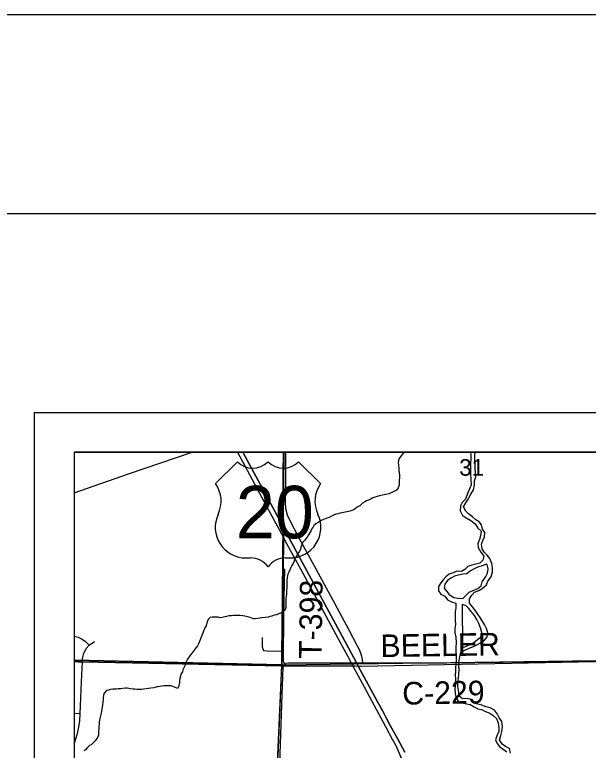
# Model space of a CAD drawing. Extents: x 0 to 34, y 0 to 22.
# Drawn here: x 1.951 to 3.392, y 20.151 to 22 of the extents above; entities that cross this region are included whole.
import ezdxf

# ---------------------------------------------------------------- set-up
doc = ezdxf.new("R2010")
doc.units = 0
for name, color, linetype in [('Default', 7, 'Continuous'), ('GM_X_County_Road', 7, 'Continuous'), ('GM_X_County_Road_Text', 7, 'Continuous'), ('GM_X_Minor_River', 7, 'Continuous'), ('GM_X_Rail_Line', 7, 'Continuous'), ('GM_X_Section', 7, 'Continuous'), ('GM_X_Section_Text', 7, 'Continuous'), ('GM_X_State_Route', 7, 'Continuous'), ('GM_X_Township', 7, 'Continuous'), ('GM_X_Township_Road', 7, 'Continuous'), ('GM_X_Township_Road_Text', 7, 'Continuous'), ('GM_X_US_Location', 7, 'Continuous'), ('GM_X_US_Route', 7, 'Continuous'), ('GM_X_US_Shield', 7, 'Continuous'), ('SH_Border', 7, 'Continuous'), ('SH_Cut_Line', 7, 'Continuous'), ('SH_Data', 7, 'Continuous')]:
    doc.layers.add(name, color=color, linetype=linetype)

msp = doc.modelspace()

# ---------------------------------------------------------------- linework, layer by layer
at = {"layer": 'Default'}
for points in [[(2.6268, 20.9), (2.1, 20.9), (2.1, 20.3771), (2.6217, 20.3656)], [(3.5755, 20.9), (2.6268, 20.9), (2.6217, 20.3656), (3.5337, 20.3786), (3.5682, 20.3787)], [(2.1, 20.3771), (2.1, 19.4698), (2.5849, 19.435), (2.5858, 19.465), (2.6217, 20.3656)]]:
    msp.add_lwpolyline(points, close=True, dxfattribs=at)
at = {"layer": 'GM_X_County_Road'}
for points in [[(2.6318, 20.8381), (2.6319, 20.845), (2.6325, 20.9)], [(2.8252, 20.371), (2.8244, 20.3793), (2.8229, 20.3867), (2.8211, 20.3926), (2.8169, 20.4035), (2.8116, 20.4141), (2.8023, 20.4319), (2.7893, 20.4563), (2.7742, 20.4842), (2.7549, 20.5196), (2.7291, 20.5675), (2.6991, 20.6232), (2.6702, 20.6767), (2.6452, 20.7228), (2.636, 20.7416), (2.6318, 20.7577), (2.6309, 20.7748), (2.6318, 20.8381)], [(2.6108, 19.9494), (2.6132, 19.9909), (2.6147, 20.0477), (2.6187, 20.1666), (2.6231, 20.2904), (2.6255, 20.36), (2.6264, 20.3623)], [(2.6264, 20.3623), (2.6267, 20.3631), (2.6272, 20.3641), (2.6302, 20.3677), (2.6333, 20.3698), (2.6391, 20.3707), (2.7004, 20.3706), (2.774, 20.3708), (2.7959, 20.3711), (2.8099, 20.3709), (2.8252, 20.371)], [(2.8252, 20.371), (3.0357, 20.3712), (3.3911, 20.375), (3.494, 20.3761), (3.5359, 20.3762)]]:
    msp.add_lwpolyline(points, dxfattribs=at)
at = {"layer": 'GM_X_Minor_River'}
msp.add_line((3.0747, 20.5174), (3.0759, 20.4092), dxfattribs=at)
for points in [[(2.9285, 20.9), (2.9251, 20.8954), (2.9209, 20.8901), (2.917, 20.8845), (2.9151, 20.8795), (2.9146, 20.8735), (2.9149, 20.8682), (2.9156, 20.8587), (2.9159, 20.8545), (2.9166, 20.8488), (2.9173, 20.8427), (2.9171, 20.823), (2.9166, 20.8173), (2.9147, 20.8108), (2.9104, 20.8048), (2.902, 20.8003), (2.8967, 20.7985), (2.8906, 20.7955), (2.8837, 20.7937), (2.875, 20.7919), (2.8678, 20.7908), (2.8617, 20.789), (2.8556, 20.7872), (2.851, 20.7853), (2.8461, 20.7831), (2.84, 20.7801), (2.8346, 20.7779), (2.8304, 20.7753), (2.8251, 20.7723), (2.8189, 20.7663), (2.8128, 20.7626), (2.8082, 20.7592), (2.8029, 20.7551), (2.7983, 20.7536), (2.7941, 20.7522), (2.7854, 20.75), (2.7812, 20.7493), (2.7732, 20.7482), (2.7679, 20.7467), (2.7633, 20.7457), (2.758, 20.7442), (2.7515, 20.7416), (2.7469, 20.7394), (2.7412, 20.7364), (2.7355, 20.7346), (2.7313, 20.7331), (2.7271, 20.7312), (2.721, 20.7286), (2.7134, 20.7238), (2.7073, 20.7201), (2.7027, 20.7163), (2.6996, 20.7114), (2.6957, 20.7061), (2.6945, 20.7016), (2.6918, 20.6971), (2.6887, 20.6922), (2.686, 20.6869), (2.6822, 20.6824), (2.6787, 20.6782), (2.6749, 20.6741), (2.6725, 20.6684), (2.6702, 20.6616), (2.6686, 20.6559), (2.6659, 20.6499), (2.662, 20.6446), (2.6574, 20.6363)], [(3.0962, 20.9), (3.0965, 20.8912), (3.0966, 20.8817), (3.0964, 20.8715), (3.096, 20.8582), (3.0964, 20.8453), (3.0972, 20.8316), (3.0976, 20.8186), (3.0935, 20.8081), (3.0883, 20.7965), (3.0833, 20.7826), (3.0755, 20.7737), (3.0707, 20.7651), (3.07, 20.753), (3.0762, 20.7414), (3.087, 20.7343), (3.0967, 20.7283), (3.1075, 20.7204), (3.1147, 20.7096), (3.1225, 20.7014), (3.1214, 20.69), (3.1185, 20.681), (3.1148, 20.6705), (3.1157, 20.6609), (3.1222, 20.6486), (3.1295, 20.6389), (3.1273, 20.6287), (3.1196, 20.6217), (3.1093, 20.619), (3.099, 20.6166), (3.089, 20.6131), (3.0816, 20.6057), (3.0731, 20.6002), (3.0618, 20.6013), (3.0522, 20.5974), (3.0426, 20.5935), (3.0341, 20.5873), (3.027, 20.5798), (3.0215, 20.572), (3.016, 20.5623), (3.016, 20.5517), (3.0219, 20.5432), (3.0316, 20.5387), (3.0386, 20.5294), (3.0483, 20.5242), (3.0588, 20.5205), (3.0596, 20.5091), (3.0578, 20.4989), (3.0572, 20.4894), (3.0577, 20.4788), (3.0581, 20.467), (3.0571, 20.4575), (3.0568, 20.4461), (3.0595, 20.4354), (3.0603, 20.4214), (3.0596, 20.4104), (3.0593, 20.3994), (3.0601, 20.3853), (3.0601, 20.3728), (3.0586, 20.3599), (3.0584, 20.3504), (3.0577, 20.3402), (3.0582, 20.3307), (3.0582, 20.3174)], [(3.088, 20.2812), (3.0758, 20.2804), (3.0677, 20.2867), (3.0668, 20.297), (3.0645, 20.3119), (3.0641, 20.3218), (3.0662, 20.332), (3.0669, 20.3426), (3.0672, 20.3532), (3.0671, 20.3642), (3.0678, 20.3756), (3.0696, 20.3862), (3.0718, 20.3979), (3.0818, 20.4029), (3.0929, 20.4079), (3.1037, 20.4122), (3.114, 20.4168), (3.1229, 20.4223), (3.131, 20.4281), (3.1381, 20.4363), (3.1395, 20.4461), (3.1363, 20.4569), (3.1309, 20.4669), (3.1255, 20.4761), (3.12, 20.485), (3.1146, 20.4928), (3.1091, 20.5009), (3.1007, 20.5114), (3.0937, 20.5211), (3.0936, 20.5313), (3.0992, 20.5407), (3.1058, 20.5484), (3.1166, 20.5527), (3.1254, 20.5578), (3.1363, 20.567), (3.1399, 20.576), (3.1482, 20.5872), (3.1516, 20.5996), (3.1515, 20.6106), (3.1495, 20.6205), (3.1449, 20.6328), (3.1379, 20.6414), (3.1309, 20.648), (3.1255, 20.6573), (3.1239, 20.6687), (3.1272, 20.6781), (3.1312, 20.6875), (3.1319, 20.6981), (3.126, 20.7066), (3.1237, 20.7173), (3.1178, 20.7254), (3.1092, 20.7306), (3.1007, 20.7377), (3.0914, 20.7455), (3.0844, 20.7522), (3.0783, 20.7626), (3.0842, 20.7734), (3.0902, 20.7824), (3.0973, 20.7947), (3.1033, 20.8056), (3.1059, 20.8177), (3.1062, 20.8283), (3.1091, 20.8381), (3.109, 20.8483), (3.1074, 20.8594), (3.1077, 20.8704), (3.1069, 20.8822), (3.1072, 20.8932), (3.1076, 20.9)], [(2.6574, 20.6363), (2.6547, 20.631), (2.6531, 20.6265), (2.6504, 20.6201), (2.6473, 20.6156), (2.6446, 20.6107), (2.6418, 20.6046), (2.6399, 20.5986), (2.6375, 20.594), (2.636, 20.5895), (2.6355, 20.5853), (2.6347, 20.5781), (2.635, 20.572), (2.6346, 20.566), (2.6345, 20.5584), (2.6341, 20.5538), (2.634, 20.5481), (2.6336, 20.544), (2.6327, 20.5375), (2.6323, 20.5322), (2.6319, 20.528), (2.6318, 20.5231), (2.6321, 20.5189), (2.6325, 20.5144), (2.632, 20.5098), (2.6304, 20.5038), (2.6243, 20.4993), (2.6186, 20.4959), (2.6133, 20.4937), (2.6083, 20.4918), (2.6026, 20.4904), (2.5969, 20.4885), (2.5923, 20.4875), (2.5881, 20.486), (2.5798, 20.4846), (2.5722, 20.4839), (2.568, 20.4832), (2.5551, 20.4818), (2.5509, 20.4818), (2.5422, 20.485), (2.5362, 20.4865), (2.5294, 20.4881), (2.5237, 20.489), (2.5165, 20.4894), (2.51, 20.4902), (2.5009, 20.49), (2.4956, 20.4893), (2.4888, 20.4886), (2.4831, 20.4875), (2.4789, 20.4864), (2.4724, 20.4849), (2.4664, 20.4843), (2.4614, 20.4854), (2.447, 20.4856), (2.4417, 20.4849), (2.4379, 20.4804), (2.4344, 20.4747), (2.4316, 20.4641), (2.4289, 20.4588), (2.4254, 20.4505), (2.4238, 20.4456), (2.4211, 20.4392), (2.4176, 20.4309), (2.4152, 20.4248), (2.4125, 20.4188), (2.4098, 20.4139), (2.4067, 20.4097), (2.3967, 20.3962), (2.3928, 20.3909), (2.389, 20.386), (2.3851, 20.38), (2.3816, 20.3732), (2.3801, 20.3686), (2.3781, 20.3633), (2.3731, 20.3532), (2.3726, 20.3478), (2.3684, 20.3422), (2.3672, 20.3373), (2.366, 20.3312), (2.3648, 20.3255), (2.3647, 20.3214), (2.3631, 20.3119), (2.36, 20.3066), (2.3521, 20.3093), (2.3438, 20.3128), (2.3396, 20.3133), (2.3294, 20.3134), (2.3252, 20.313), (2.3206, 20.312), (2.3157, 20.3112), (2.3085, 20.3102), (2.3005, 20.308), (2.2929, 20.3073), (2.2872, 20.3066), (2.2743, 20.3049), (2.2693, 20.3038), (2.2576, 20.3039), (2.253, 20.3043), (2.2488, 20.3044), (2.242, 20.3056), (2.2337, 20.3068)], [(3.135, 20.619), (3.1258, 20.6143), (3.1163, 20.6119), (3.1071, 20.6076), (3.0959, 20.6019), (3.0866, 20.5945), (3.0771, 20.5937), (3.0657, 20.5913), (3.0561, 20.5889), (3.0465, 20.5839), (3.0384, 20.5776), (3.0313, 20.5683), (3.0295, 20.5585), (3.0369, 20.5503), (3.0427, 20.5422), (3.0539, 20.5351), (3.0652, 20.5332), (3.077, 20.5325), (3.0844, 20.5399), (3.0926, 20.5488), (3.1029, 20.5527), (3.1144, 20.5573), (3.1229, 20.5643), (3.1251, 20.5741), (3.1275, 20.5778)], [(3.1275, 20.5778), (3.1346, 20.5879), (3.139, 20.5965), (3.1404, 20.6075), (3.138, 20.6174), (3.135, 20.619)], [(3.0759, 20.4092), (3.0847, 20.412), (3.0943, 20.4166), (3.1043, 20.4217), (3.114, 20.4298), (3.1233, 20.4367), (3.1247, 20.4473), (3.1212, 20.4584), (3.1173, 20.4695), (3.1123, 20.4799), (3.1058, 20.4896), (3.0981, 20.4997), (3.0918, 20.5078), (3.0848, 20.5145), (3.0747, 20.5174)], [(2.2337, 20.3068), (2.2295, 20.3069), (2.2227, 20.3062), (2.2174, 20.3055), (2.2113, 20.3055), (2.2064, 20.3048), (2.2014, 20.3045), (2.1972, 20.3042), (2.1916, 20.3035), (2.1866, 20.3024), (2.1817, 20.3009), (2.1759, 20.2949), (2.1739, 20.2896), (2.1735, 20.2824), (2.1731, 20.2779), (2.1726, 20.2722), (2.1718, 20.265), (2.1709, 20.2593), (2.1697, 20.254), (2.1689, 20.249), (2.1685, 20.2445), (2.1661, 20.2373), (2.1641, 20.2278), (2.1633, 20.2214), (2.1629, 20.2161), (2.162, 20.2104), (2.162, 20.2062), (2.1615, 20.1975), (2.1614, 20.1888), (2.1591, 20.1831), (2.1529, 20.1744), (2.1479, 20.1696), (2.1433, 20.165), (2.1391, 20.1628), (2.1341, 20.1583), (2.1295, 20.1527), (2.1253, 20.1493)], [(3.0582, 20.3174), (3.0568, 20.3056), (3.0576, 20.2931), (3.06, 20.2828), (3.0647, 20.2743), (3.0752, 20.2702), (3.0857, 20.2676), (3.0952, 20.2662), (3.1053, 20.2606), (3.1146, 20.2555), (3.124, 20.2537), (3.1341, 20.2485), (3.145, 20.2444), (3.1528, 20.2385), (3.1617, 20.231), (3.1656, 20.2199), (3.1675, 20.2081), (3.1673, 20.1986), (3.1624, 20.1877), (3.1591, 20.1775), (3.163, 20.1683), (3.1689, 20.1606), (3.1778, 20.1539), (3.1871, 20.1471)], [(3.1969, 20.1435), (3.1938, 20.1553), (3.1841, 20.1609), (3.1759, 20.1661), (3.169, 20.1769), (3.1723, 20.1878), (3.1745, 20.198), (3.1763, 20.2105), (3.1748, 20.2234), (3.1678, 20.2331), (3.1635, 20.2416), (3.1566, 20.2516), (3.1454, 20.2573), (3.1356, 20.2606), (3.1243, 20.2643), (3.1145, 20.2668), (3.1028, 20.2694), (3.0981, 20.2783), (3.088, 20.2812)]]:
    msp.add_lwpolyline(points, dxfattribs=at)
at = {"layer": 'GM_X_Rail_Line'}
msp.add_lwpolyline([(2.1, 20.7981), (2.2372, 20.8459), (2.3967, 20.9)], dxfattribs=at)
at = {"layer": 'GM_X_Section'}
msp.add_lwpolyline([(3.5337, 20.3786), (3.5253, 19.4614), (2.5858, 19.465), (2.6217, 20.3656)], close=True, dxfattribs=at)
at = {"layer": 'GM_X_State_Route'}
for points in [[(2.8099, 20.3709), (2.8028, 20.3833), (2.7901, 20.407), (2.6407, 20.6842), (2.626, 20.7111), (2.6059, 20.7484), (2.5732, 20.8088), (2.524, 20.9)], [(2.9307, 20.1466), (2.9125, 20.1804), (2.8946, 20.2135), (2.8835, 20.234), (2.8754, 20.2489), (2.8624, 20.2731), (2.839, 20.3163), (2.8142, 20.3623), (2.8099, 20.3709)]]:
    msp.add_lwpolyline(points, dxfattribs=at)
at = {"layer": 'GM_X_Township'}
msp.add_lwpolyline([(2.5093, 17.4289), (2.5256, 18.0846), (2.5616, 18.9348), (2.5619, 18.941), (2.5631, 18.9701), (2.6034, 19.9491), (2.6035, 19.9525), (2.6217, 20.3636), (2.6265, 20.3636), (2.7999, 20.363), (2.8069, 20.3629), (2.814, 20.3628), (2.8217, 20.3627), (3.5356, 20.3768), (3.5731, 20.3768), (3.6279, 20.3774), (4.0307, 20.3846), (4.54, 20.3955), (4.5784, 20.3968), (5.284, 20.4086)], dxfattribs=at)
at = {"layer": 'GM_X_Township_Road'}
for p, q in [((2.6282, 20.5327), (2.6294, 20.6067)), ((2.1, 20.2446), (2.1152, 20.2435))]:
    msp.add_line(p, q, dxfattribs=at)
msp.add_lwpolyline([(2.6262, 20.9), (2.1, 20.9), (2.1, 20.3739), (2.1108, 20.3737), (2.1208, 20.3735), (2.6217, 20.3636), (2.622, 20.3702), (2.6222, 20.3879), (2.6224, 20.4009), (2.6254, 20.6074), (2.6259, 20.6758), (2.6259, 20.6863), (2.6258, 20.7117), (2.6258, 20.7122), (2.6255, 20.8483)], close=True, dxfattribs=at)
for points in [[(8.5676, 20.9), (2.6262, 20.9), (2.6255, 20.8483), (2.6258, 20.7122), (2.6258, 20.7117), (2.6259, 20.6863), (2.6259, 20.6758), (2.6254, 20.6074), (2.6224, 20.4009), (2.6222, 20.3879), (2.622, 20.3702), (2.6217, 20.3636), (2.6265, 20.3636), (2.7999, 20.363), (2.8069, 20.3629), (2.814, 20.3628), (2.8217, 20.3627), (3.5356, 20.3768), (3.5731, 20.3768), (3.6279, 20.3774), (4.0307, 20.3846), (4.54, 20.3955), (4.5784, 20.3968), (5.284, 20.4086)], [(2.6302, 20.3677), (2.6274, 20.3716), (2.6259, 20.3765), (2.6261, 20.4003), (2.6271, 20.4688), (2.6282, 20.5327)], [(2.1, 20.438), (2.1103, 20.4353), (2.1205, 20.4304), (2.1285, 20.4243), (2.1377, 20.4153)], [(2.573, 20.4348), (2.5724, 20.4114), (2.5763, 20.402), (2.5851, 20.4008), (2.6226, 20.4004), (2.6261, 20.4003)], [(2.1212, 20.3758), (2.1215, 20.3806), (2.1227, 20.3883), (2.1249, 20.3952), (2.1276, 20.4012), (2.1308, 20.4066), (2.1377, 20.4153), (2.1517, 20.4242)], [(2.1, 20.1664), (2.1091, 20.1931), (2.1124, 20.2096), (2.1144, 20.2238), (2.1152, 20.2435), (2.1161, 20.2625), (2.1187, 20.3232), (2.1211, 20.3729), (2.1212, 20.3758)], [(2.4116, 15.0173), (2.4334, 15.5145), (2.4339, 15.5244), (2.4986, 16.925), (2.5003, 16.9626), (2.5093, 17.4289), (2.5256, 18.0846), (2.5616, 18.9348), (2.5619, 18.941), (2.5631, 18.9701), (2.6034, 19.9491), (2.6035, 19.9525), (2.6217, 20.3636), (2.1208, 20.3735), (2.1108, 20.3737), (2.1, 20.3739), (2.1, 14.5206)]]:
    msp.add_lwpolyline(points, dxfattribs=at)
at = {"layer": 'GM_X_US_Route'}
for points in [[(2.5106, 20.9), (2.5962, 20.7414), (2.6261, 20.6857), (2.63, 20.6785), (2.6686, 20.6069)], [(2.524, 20.9), (2.5732, 20.8088), (2.6059, 20.7484), (2.626, 20.7111), (2.6407, 20.6842), (2.7901, 20.407), (2.8028, 20.3833), (2.8099, 20.3709)], [(2.6686, 20.6069), (2.7685, 20.4218), (2.7868, 20.3881), (2.7959, 20.3711)], [(2.7959, 20.3711), (2.8001, 20.3625), (2.8038, 20.3567), (2.8286, 20.3105), (2.8537, 20.2639), (2.865, 20.2431), (2.8827, 20.2104), (2.9004, 20.1773), (2.9019, 20.1745)], [(2.8099, 20.3709), (2.8142, 20.3623), (2.839, 20.3163), (2.8624, 20.2731), (2.8754, 20.2489), (2.8835, 20.234), (2.8946, 20.2135), (2.9125, 20.1804), (2.9307, 20.1466)], [(2.9019, 20.1745), (2.9081, 20.1626), (2.9168, 20.144), (2.9255, 20.1228), (2.9329, 20.1006), (2.9369, 20.0855), (2.9383, 20.0796)]]:
    msp.add_lwpolyline(points, dxfattribs=at)
at = {"layer": 'GM_X_US_Shield'}
for p, q in [((2.5105, 20.8761), (2.4556, 20.8212)), ((2.7192, 20.8212), (2.6643, 20.8761)), ((2.5325, 20.6344), (2.5434, 20.6344)), ((2.6313, 20.6344), (2.6423, 20.6344))]:
    msp.add_line(p, q, dxfattribs=at)
for centre, radius, start, end in [((2.5489, 20.9153), 0.0549, 225.573, 314.427), ((2.6258, 20.9153), 0.0549, 225.573, 314.427), ((2.3926, 20.7771), 0.0769, 334.5471, 35.0009), ((2.7822, 20.7771), 0.0769, 144.9991, 205.4529), ((2.5316, 20.7113), 0.0769, 154.8319, 270.6383), ((2.6432, 20.7113), 0.0769, 269.3617, 25.1681), ((2.5434, 20.5795), 0.0549, 36.8699, 90), ((2.6313, 20.5795), 0.0549, 90, 143.1301)]:
    msp.add_arc(centre, radius, start, end, dxfattribs=at)
at = {"layer": 'SH_Border'}
msp.add_lwpolyline([(1.5, 21.5), (33.5, 21.5), (33.5, 0.5), (1.5, 0.5)], close=True, dxfattribs=at)
at = {"layer": 'SH_Cut_Line'}
msp.add_lwpolyline([(0, 0), (34, 0), (34, 22), (0, 22)], close=True, dxfattribs=at)
msp.add_lwpolyline([(8.9, 20.9), (2.1, 20.9), (2.1, 14.5206)], dxfattribs=at)
at = {"layer": 'SH_Data'}
for p, q in [((2, 21), (9, 21)), ((2, 21), (2, 14)), ((2.1, 20.9), (2.1, 14.1)), ((2.1, 20.9), (8.9, 20.9))]:
    msp.add_line(p, q, dxfattribs=at)

# ---------------------------------------------------------------- texts
at = {"layer": 'GM_X_County_Road_Text'}
for s, rotation, p in [('BEELER', 0.9092, (2.8704, 20.385)), ('C-229', 1.1016, (2.9251, 20.2655))]:
    msp.add_text(s, height=0.05682, rotation=rotation, dxfattribs=at).set_placement(p)
at = {"layer": 'GM_X_Section_Text'}
msp.add_text('31', height=0.04186, rotation=0, dxfattribs=at).set_placement((3.0678, 20.841))
at = {"layer": 'GM_X_Township_Road_Text'}
msp.add_text('T-398', height=0.05682, rotation=89.1679, dxfattribs=at).set_placement((2.7218, 20.3806))
at = {"layer": 'GM_X_US_Location'}
for s in ['0', '/']:
    msp.add_text(s, height=0.000189, dxfattribs=at).set_placement((2.5873, 20.7487))
msp.add_text('20', height=0.000189, rotation=0, dxfattribs=at).set_placement((2.5482, 20.7095))
at = {"layer": 'GM_X_US_Shield'}
msp.add_text('20', height=0.13184, dxfattribs=at).set_placement((2.5065, 20.6838))

doc.saveas('drawing.dxf')
